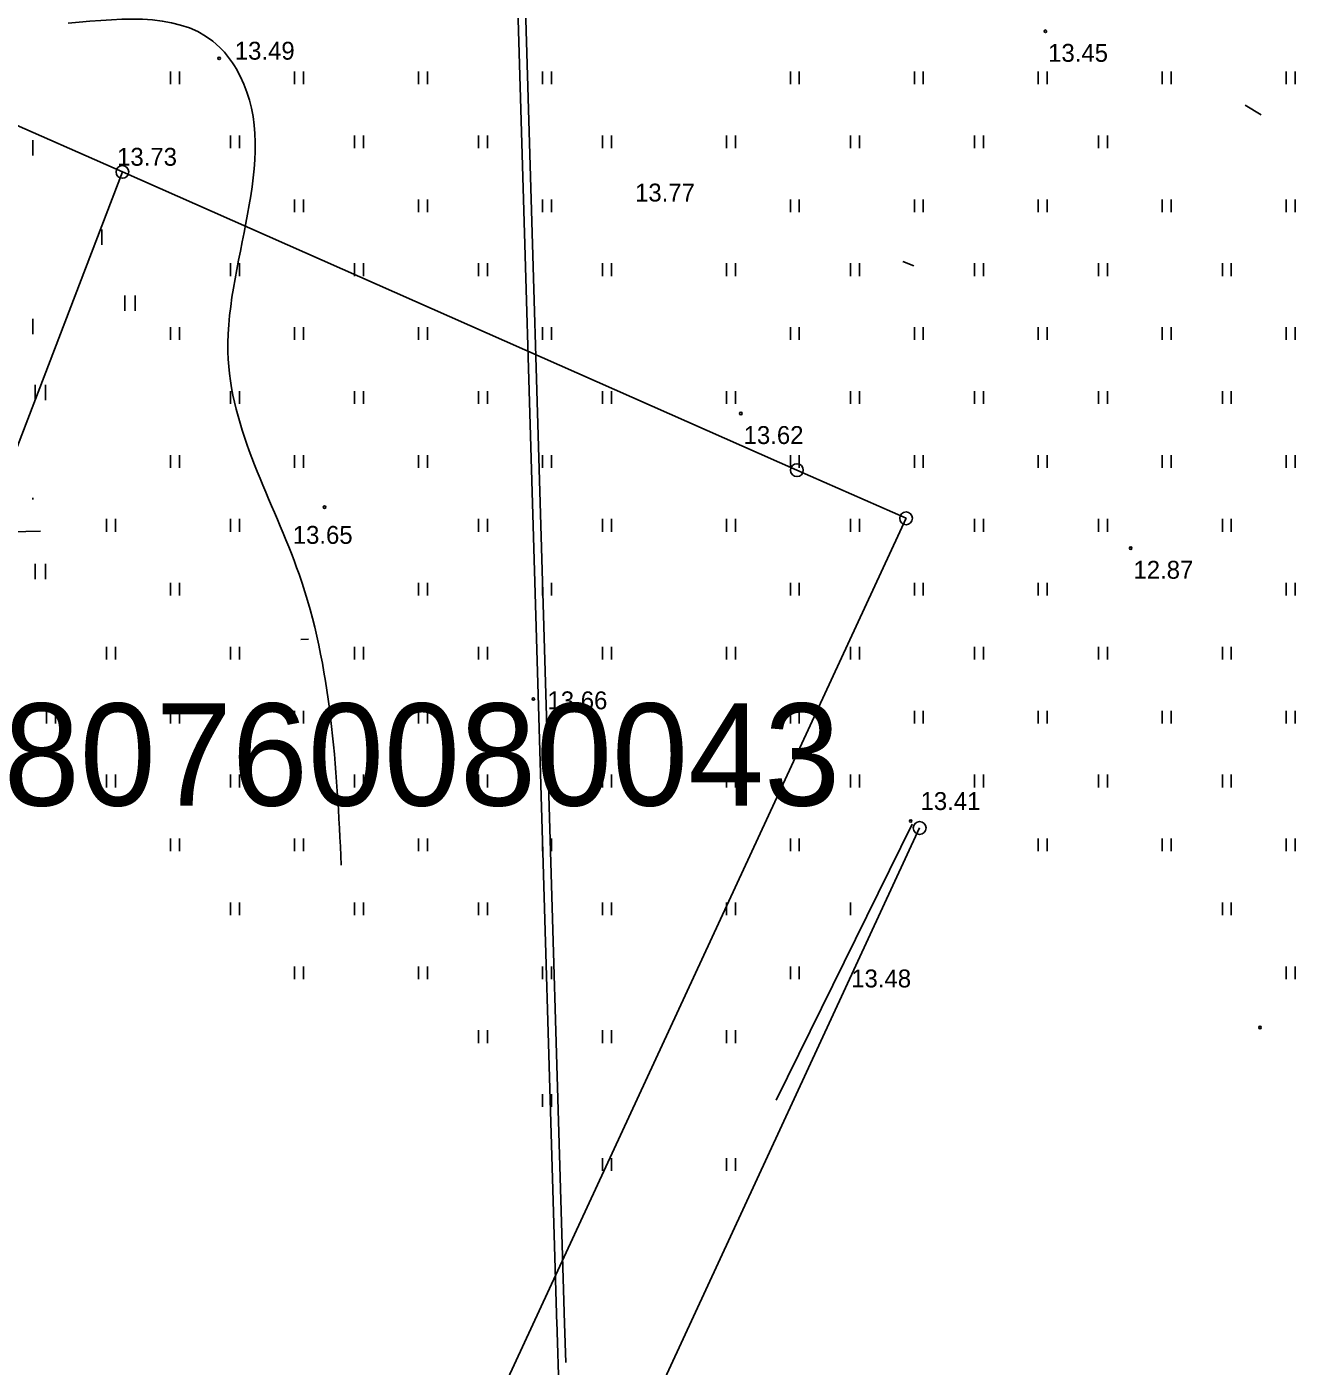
# Model space of a CAD drawing. Extents: x 503877 to 504025, y 304562 to 304725.
# Drawn here: x 503975.2 to 504024.9, y 304606.3 to 304658.7 of the extents above; entities that cross this region are included whole.
import ezdxf

# ---------------------------------------------------------------- set-up
doc = ezdxf.new("R2010")
doc.units = 0
for name, color, linetype in [('10', 7, 'Continuous'), ('24', 7, 'Continuous'), ('25', 7, 'Continuous'), ('NORB_ZOGS_ZSTP_####_#', 7, 'Continuous'), ('RELJ_AATZ_####_TKST_#', 7, 'Continuous'), ('RELJ_ELEM_####_####_#', 7, 'Continuous'), ('RELJ_HORZ_KRIT_####_#', 7, 'Continuous'), ('RELJ_HORZ_PAMT_####_#', 7, 'Continuous'), ('SAKT_VADP_KABE_####_#', 7, 'Continuous'), ('TERT_ELEM_####_####_#', 7, 'Continuous')]:
    doc.layers.add(name, color=color, linetype=linetype)

msp = doc.modelspace()

# ---------------------------------------------------------------- linework, layer by layer
at = {"layer": '10'}
for centre in [(503978.978, 304653.014), (504005.364, 304641.349), (504009.636, 304639.466), (504010.166, 304627.354)]:
    msp.add_circle(centre, 0.25, dxfattribs=at)
at = {"layer": '24'}
for p, q in [((503952.592, 304664.678), (503978.978, 304653.014)), ((503978.978, 304653.014), (503960.823, 304605.633)), ((504005.364, 304641.349), (503978.978, 304653.014)), ((503987.744, 304578.935), (504010.166, 304627.354))]:
    msp.add_line(p, q, dxfattribs=at)
at = {"layer": '25'}
for p, q in [((504009.636, 304639.466), (504005.364, 304641.349)), ((503983.332, 304582.665), (504009.636, 304639.466))]:
    msp.add_line(p, q, dxfattribs=at)
at = {"layer": 'NORB_ZOGS_ZSTP_####_#'}
msp.add_line((504009.868, 304627.5), (504004.555, 304616.709), dxfattribs=at)
at = {"layer": 'RELJ_ELEM_####_####_#'}
for centre in [(504015.087, 304658.517), (503982.761, 304657.457), (504003.174, 304643.566), (503986.887, 304639.904), (504018.424, 304638.298), (503995.057, 304632.4), (504009.816, 304627.625), (504023.484, 304619.549)]:
    msp.add_circle(centre, 0.05, dxfattribs=at)
at = {"layer": 'RELJ_HORZ_KRIT_####_#'}
for p, q in [((504022.906, 304655.625), (504023.53, 304655.253)), ((504009.509, 304649.51), (504009.938, 304649.343)), ((503986.259, 304634.74), (503985.956, 304634.724))]:
    msp.add_line(p, q, dxfattribs=at)
at = {"layer": 'RELJ_HORZ_PAMT_####_#'}
for points in [[(503987.539, 304625.902), (503985.892, 304637.275), (503983.106, 304645.98), (503983.425, 304657.056), (503982.792, 304657.882), (503976.857, 304658.83)], [(503958.259, 304644.072), (503959.691, 304642.482), (503975.774, 304638.957)]]:
    msp.add_spline(points, degree=3, dxfattribs=at)
at = {"layer": 'SAKT_VADP_KABE_####_#'}
for p, q in [((503993.253, 304709.476), (503996.275, 304607.968)), ((503992.977, 304708.659), (503995.977, 304607.917)), ((503995.972, 304608.066), (503996.06, 304605.117)), ((503996.321, 304606.451), (503996.275, 304607.968))]:
    msp.add_line(p, q, dxfattribs=at)
at = {"layer": 'TERT_ELEM_####_####_#'}
for p, q in [((503980.86, 304656.441), (503980.86, 304656.941)), ((503981.21, 304656.441), (503981.21, 304656.941)), ((503985.71, 304656.441), (503985.71, 304656.941)), ((503986.06, 304656.441), (503986.06, 304656.941)), ((503990.56, 304656.441), (503990.56, 304656.941)), ((503990.91, 304656.441), (503990.91, 304656.941)), ((503995.41, 304656.441), (503995.41, 304656.941)), ((503995.76, 304656.441), (503995.76, 304656.941)), ((504005.11, 304656.441), (504005.11, 304656.941)), ((504005.46, 304656.441), (504005.46, 304656.941)), ((504009.96, 304656.441), (504009.96, 304656.941)), ((504010.31, 304656.441), (504010.31, 304656.941)), ((504014.81, 304656.441), (504014.81, 304656.941)), ((504015.16, 304656.441), (504015.16, 304656.941)), ((504019.66, 304656.441), (504019.66, 304656.941)), ((504020.01, 304656.441), (504020.01, 304656.941)), ((504024.51, 304656.441), (504024.51, 304656.941)), ((504024.86, 304656.441), (504024.86, 304656.941)), ((503975.479, 304653.662), (503975.479, 304654.262)), ((503983.21, 304653.941), (503983.21, 304654.441)), ((503983.56, 304653.941), (503983.56, 304654.441)), ((503988.06, 304653.941), (503988.06, 304654.441)), ((503988.41, 304653.941), (503988.41, 304654.441)), ((503992.91, 304653.941), (503992.91, 304654.441)), ((503993.26, 304653.941), (503993.26, 304654.441)), ((503997.76, 304653.941), (503997.76, 304654.441)), ((503998.11, 304653.941), (503998.11, 304654.441)), ((504002.61, 304653.941), (504002.61, 304654.441)), ((504002.96, 304653.941), (504002.96, 304654.441)), ((504007.46, 304653.941), (504007.46, 304654.441)), ((504007.81, 304653.941), (504007.81, 304654.441)), ((504012.31, 304653.941), (504012.31, 304654.441)), ((504012.66, 304653.941), (504012.66, 304654.441)), ((504017.16, 304653.941), (504017.16, 304654.441)), ((504017.51, 304653.941), (504017.51, 304654.441)), ((503985.71, 304651.441), (503985.71, 304651.941)), ((503986.06, 304651.441), (503986.06, 304651.941)), ((503990.56, 304651.441), (503990.56, 304651.941)), ((503990.91, 304651.441), (503990.91, 304651.941)), ((503995.41, 304651.441), (503995.41, 304651.941)), ((503995.76, 304651.441), (503995.76, 304651.941)), ((504005.11, 304651.441), (504005.11, 304651.941)), ((504005.46, 304651.441), (504005.46, 304651.941)), ((504009.96, 304651.441), (504009.96, 304651.941)), ((504010.31, 304651.441), (504010.31, 304651.941)), ((504014.81, 304651.441), (504014.81, 304651.941)), ((504015.16, 304651.441), (504015.16, 304651.941)), ((504019.66, 304651.441), (504019.66, 304651.941)), ((504020.01, 304651.441), (504020.01, 304651.941)), ((504024.51, 304651.441), (504024.51, 304651.941)), ((504024.86, 304651.441), (504024.86, 304651.941)), ((503978.179, 304650.162), (503978.179, 304650.762)), ((503983.21, 304648.941), (503983.21, 304649.441)), ((503983.56, 304648.941), (503983.56, 304649.441)), ((503988.06, 304648.941), (503988.06, 304649.441)), ((503988.41, 304648.941), (503988.41, 304649.441)), ((503992.91, 304648.941), (503992.91, 304649.441)), ((503993.26, 304648.941), (503993.26, 304649.441)), ((503997.76, 304648.941), (503997.76, 304649.441)), ((503998.11, 304648.941), (503998.11, 304649.441)), ((504002.61, 304648.941), (504002.61, 304649.441)), ((504002.96, 304648.941), (504002.96, 304649.441)), ((504007.46, 304648.941), (504007.46, 304649.441)), ((504007.81, 304648.941), (504007.81, 304649.441)), ((504012.31, 304648.941), (504012.31, 304649.441)), ((504012.66, 304648.941), (504012.66, 304649.441)), ((504017.16, 304648.941), (504017.16, 304649.441)), ((504017.51, 304648.941), (504017.51, 304649.441)), ((504022.01, 304648.941), (504022.01, 304649.441)), ((504022.36, 304648.941), (504022.36, 304649.441)), ((503979.071, 304647.587), (503979.071, 304648.187)), ((503979.471, 304647.587), (503979.471, 304648.187)), ((503975.479, 304646.662), (503975.479, 304647.262)), ((503980.86, 304646.441), (503980.86, 304646.941)), ((503981.21, 304646.441), (503981.21, 304646.941)), ((503985.71, 304646.441), (503985.71, 304646.941)), ((503986.06, 304646.441), (503986.06, 304646.941)), ((503990.56, 304646.441), (503990.56, 304646.941)), ((503990.91, 304646.441), (503990.91, 304646.941)), ((503995.41, 304646.441), (503995.41, 304646.941)), ((503995.76, 304646.441), (503995.76, 304646.941)), ((504005.11, 304646.441), (504005.11, 304646.941)), ((504005.46, 304646.441), (504005.46, 304646.941)), ((504009.96, 304646.441), (504009.96, 304646.941)), ((504010.31, 304646.441), (504010.31, 304646.941)), ((504014.81, 304646.441), (504014.81, 304646.941)), ((504015.16, 304646.441), (504015.16, 304646.941)), ((504019.66, 304646.441), (504019.66, 304646.941)), ((504020.01, 304646.441), (504020.01, 304646.941)), ((504024.51, 304646.441), (504024.51, 304646.941)), ((504024.86, 304646.441), (504024.86, 304646.941)), ((503975.571, 304644.087), (503975.571, 304644.687)), ((503975.971, 304644.087), (503975.971, 304644.687)), ((503983.21, 304643.941), (503983.21, 304644.441)), ((503983.56, 304643.941), (503983.56, 304644.441)), ((503988.06, 304643.941), (503988.06, 304644.441)), ((503988.41, 304643.941), (503988.41, 304644.441)), ((503992.91, 304643.941), (503992.91, 304644.441)), ((503993.26, 304643.941), (503993.26, 304644.441)), ((503997.76, 304643.941), (503997.76, 304644.441)), ((503998.11, 304643.941), (503998.11, 304644.441)), ((504002.61, 304643.941), (504002.61, 304644.441)), ((504002.96, 304643.941), (504002.96, 304644.441)), ((504007.46, 304643.941), (504007.46, 304644.441)), ((504007.81, 304643.941), (504007.81, 304644.441)), ((504012.31, 304643.941), (504012.31, 304644.441)), ((504012.66, 304643.941), (504012.66, 304644.441)), ((504017.16, 304643.941), (504017.16, 304644.441)), ((504017.51, 304643.941), (504017.51, 304644.441)), ((504022.01, 304643.941), (504022.01, 304644.441)), ((504022.36, 304643.941), (504022.36, 304644.441)), ((503980.86, 304641.441), (503980.86, 304641.941)), ((503981.21, 304641.441), (503981.21, 304641.941)), ((503985.71, 304641.441), (503985.71, 304641.941)), ((503986.06, 304641.441), (503986.06, 304641.941)), ((503990.56, 304641.441), (503990.56, 304641.941)), ((503990.91, 304641.441), (503990.91, 304641.941)), ((503995.41, 304641.441), (503995.41, 304641.941)), ((503995.76, 304641.441), (503995.76, 304641.941)), ((504005.11, 304641.441), (504005.11, 304641.941)), ((504005.46, 304641.441), (504005.46, 304641.941)), ((504009.96, 304641.441), (504009.96, 304641.941)), ((504010.31, 304641.441), (504010.31, 304641.941)), ((504014.81, 304641.441), (504014.81, 304641.941)), ((504015.16, 304641.441), (504015.16, 304641.941)), ((504019.66, 304641.441), (504019.66, 304641.941)), ((504020.01, 304641.441), (504020.01, 304641.941)), ((504024.51, 304641.441), (504024.51, 304641.941)), ((504024.86, 304641.441), (504024.86, 304641.941)), ((503975.479, 304640.2), (503975.479, 304640.262)), ((503978.36, 304638.941), (503978.36, 304639.441)), ((503978.71, 304638.941), (503978.71, 304639.441)), ((503983.21, 304638.941), (503983.21, 304639.441)), ((503983.56, 304638.941), (503983.56, 304639.441)), ((503992.91, 304638.941), (503992.91, 304639.441)), ((503993.26, 304638.941), (503993.26, 304639.441)), ((503997.76, 304638.941), (503997.76, 304639.441)), ((503998.11, 304638.941), (503998.11, 304639.441)), ((504002.61, 304638.941), (504002.61, 304639.441)), ((504002.96, 304638.941), (504002.96, 304639.441)), ((504007.46, 304638.941), (504007.46, 304639.441)), ((504007.81, 304638.941), (504007.81, 304639.441)), ((504012.31, 304638.941), (504012.31, 304639.441)), ((504012.66, 304638.941), (504012.66, 304639.441)), ((504017.16, 304638.941), (504017.16, 304639.441)), ((504017.51, 304638.941), (504017.51, 304639.441)), ((504022.01, 304638.941), (504022.01, 304639.441)), ((504022.36, 304638.941), (504022.36, 304639.441)), ((503975.571, 304637.087), (503975.571, 304637.687)), ((503975.971, 304637.087), (503975.971, 304637.687)), ((503980.86, 304636.441), (503980.86, 304636.941)), ((503981.21, 304636.441), (503981.21, 304636.941)), ((503990.56, 304636.441), (503990.56, 304636.941)), ((503990.91, 304636.441), (503990.91, 304636.941)), ((503995.41, 304636.441), (503995.41, 304636.941)), ((503995.76, 304636.441), (503995.76, 304636.941)), ((504005.11, 304636.441), (504005.11, 304636.941)), ((504005.46, 304636.441), (504005.46, 304636.941)), ((504009.96, 304636.441), (504009.96, 304636.941)), ((504010.31, 304636.441), (504010.31, 304636.941)), ((504014.81, 304636.441), (504014.81, 304636.941)), ((504015.16, 304636.441), (504015.16, 304636.941)), ((504024.51, 304636.441), (504024.51, 304636.941)), ((504024.86, 304636.441), (504024.86, 304636.941)), ((503978.36, 304633.941), (503978.36, 304634.441)), ((503978.71, 304633.941), (503978.71, 304634.441)), ((503983.21, 304633.941), (503983.21, 304634.441)), ((503983.56, 304633.941), (503983.56, 304634.441)), ((503988.06, 304633.941), (503988.06, 304634.441)), ((503988.41, 304633.941), (503988.41, 304634.441)), ((503992.91, 304633.941), (503992.91, 304634.441)), ((503993.26, 304633.941), (503993.26, 304634.441)), ((503997.76, 304633.941), (503997.76, 304634.441)), ((503998.11, 304633.941), (503998.11, 304634.441)), ((504002.61, 304633.941), (504002.61, 304634.441)), ((504002.96, 304633.941), (504002.96, 304634.441)), ((504007.46, 304633.941), (504007.46, 304634.441)), ((504007.81, 304633.941), (504007.81, 304634.441)), ((504012.31, 304633.941), (504012.31, 304634.441)), ((504012.66, 304633.941), (504012.66, 304634.441)), ((504017.16, 304633.941), (504017.16, 304634.441)), ((504017.51, 304633.941), (504017.51, 304634.441)), ((504022.01, 304633.941), (504022.01, 304634.441)), ((504022.36, 304633.941), (504022.36, 304634.441)), ((503976.01, 304631.441), (503976.01, 304631.941)), ((503976.36, 304631.441), (503976.36, 304631.941)), ((503980.86, 304631.441), (503980.86, 304631.941)), ((503981.21, 304631.441), (503981.21, 304631.941)), ((503985.71, 304631.441), (503985.71, 304631.941)), ((503986.06, 304631.441), (503986.06, 304631.941)), ((503990.56, 304631.441), (503990.56, 304631.941)), ((503990.91, 304631.441), (503990.91, 304631.941)), ((504005.11, 304631.441), (504005.11, 304631.941)), ((504005.46, 304631.441), (504005.46, 304631.941)), ((504009.96, 304631.441), (504009.96, 304631.941)), ((504010.31, 304631.441), (504010.31, 304631.941)), ((504014.81, 304631.441), (504014.81, 304631.941)), ((504015.16, 304631.441), (504015.16, 304631.941)), ((504019.66, 304631.441), (504019.66, 304631.941)), ((504020.01, 304631.441), (504020.01, 304631.941)), ((504024.51, 304631.441), (504024.51, 304631.941)), ((504024.86, 304631.441), (504024.86, 304631.941)), ((503978.36, 304628.941), (503978.36, 304629.441)), ((503978.71, 304628.941), (503978.71, 304629.441)), ((503983.21, 304628.941), (503983.21, 304629.441)), ((503983.56, 304628.941), (503983.56, 304629.441)), ((503988.06, 304628.941), (503988.06, 304629.441)), ((503988.41, 304628.941), (503988.41, 304629.441)), ((503992.91, 304628.941), (503992.91, 304629.441)), ((503993.26, 304628.941), (503993.26, 304629.441)), ((503997.76, 304628.941), (503997.76, 304629.441)), ((503998.11, 304628.941), (503998.11, 304629.441)), ((504002.61, 304628.941), (504002.61, 304629.441)), ((504002.96, 304628.941), (504002.96, 304629.441)), ((504007.46, 304628.941), (504007.46, 304629.441)), ((504007.81, 304628.941), (504007.81, 304629.441)), ((504012.31, 304628.941), (504012.31, 304629.441)), ((504012.66, 304628.941), (504012.66, 304629.441)), ((504017.16, 304628.941), (504017.16, 304629.441)), ((504017.51, 304628.941), (504017.51, 304629.441)), ((504022.01, 304628.941), (504022.01, 304629.441)), ((504022.36, 304628.941), (504022.36, 304629.441)), ((503980.86, 304626.441), (503980.86, 304626.941)), ((503981.21, 304626.441), (503981.21, 304626.941)), ((503985.71, 304626.441), (503985.71, 304626.941)), ((503986.06, 304626.441), (503986.06, 304626.941)), ((503990.56, 304626.441), (503990.56, 304626.941)), ((503990.91, 304626.441), (503990.91, 304626.941)), ((503995.41, 304626.441), (503995.41, 304626.941)), ((503995.76, 304626.441), (503995.76, 304626.941)), ((504005.11, 304626.441), (504005.11, 304626.941)), ((504005.46, 304626.441), (504005.46, 304626.941)), ((504014.81, 304626.441), (504014.81, 304626.941)), ((504015.16, 304626.441), (504015.16, 304626.941)), ((504019.66, 304626.441), (504019.66, 304626.941)), ((504020.01, 304626.441), (504020.01, 304626.941)), ((504024.51, 304626.441), (504024.51, 304626.941)), ((504024.86, 304626.441), (504024.86, 304626.941)), ((503983.21, 304623.941), (503983.21, 304624.441)), ((503983.56, 304623.941), (503983.56, 304624.441)), ((503988.06, 304623.941), (503988.06, 304624.441)), ((503988.41, 304623.941), (503988.41, 304624.441)), ((503992.91, 304623.941), (503992.91, 304624.441)), ((503993.26, 304623.941), (503993.26, 304624.441)), ((503997.76, 304623.941), (503997.76, 304624.441)), ((503998.11, 304623.941), (503998.11, 304624.441)), ((504002.61, 304623.941), (504002.61, 304624.441)), ((504002.96, 304623.941), (504002.96, 304624.441)), ((504007.46, 304623.941), (504007.46, 304624.441)), ((504022.01, 304623.941), (504022.01, 304624.441)), ((504022.36, 304623.941), (504022.36, 304624.441)), ((503985.71, 304621.441), (503985.71, 304621.941)), ((503986.06, 304621.441), (503986.06, 304621.941)), ((503990.56, 304621.441), (503990.56, 304621.941)), ((503990.91, 304621.441), (503990.91, 304621.941)), ((503995.41, 304621.441), (503995.41, 304621.941)), ((503995.76, 304621.441), (503995.76, 304621.941)), ((504005.11, 304621.441), (504005.11, 304621.941)), ((504005.46, 304621.441), (504005.46, 304621.941)), ((504024.51, 304621.441), (504024.51, 304621.941)), ((504024.86, 304621.441), (504024.86, 304621.941)), ((503992.91, 304618.941), (503992.91, 304619.441)), ((503993.26, 304618.941), (503993.26, 304619.441)), ((503997.76, 304618.941), (503997.76, 304619.441)), ((503998.11, 304618.941), (503998.11, 304619.441)), ((504002.61, 304618.941), (504002.61, 304619.441)), ((504002.96, 304618.941), (504002.96, 304619.441)), ((503995.41, 304616.441), (503995.41, 304616.941)), ((503995.76, 304616.441), (503995.76, 304616.941)), ((503997.76, 304613.941), (503997.76, 304614.441)), ((503998.11, 304613.941), (503998.11, 304614.441)), ((504002.61, 304613.941), (504002.61, 304614.441)), ((504002.96, 304613.941), (504002.96, 304614.441))]:
    msp.add_line(p, q, dxfattribs=at)

# ---------------------------------------------------------------- texts
at = {"layer": '24'}
msp.add_text('80760080043', height=4, dxfattribs=at).set_placement((503974.335, 304628.227))
at = {"layer": 'RELJ_AATZ_####_TKST_#'}
for s, p in [('13.49', (503983.375, 304657.405)), ('13.45', (504015.194, 304657.322)), ('13.73', (503978.77, 304653.256)), ('13.77', (503999.033, 304651.857)), ('13.62', (504003.281, 304642.372)), ('13.65', (503985.642, 304638.468)), ('12.87', (504018.531, 304637.103)), ('13.66', (503995.608, 304631.996)), ('13.41', (504010.203, 304628.057)), ('13.48', (504007.49, 304621.117))]:
    msp.add_text(s, height=0.7, dxfattribs=at).set_placement(p)

doc.saveas('drawing.dxf')
